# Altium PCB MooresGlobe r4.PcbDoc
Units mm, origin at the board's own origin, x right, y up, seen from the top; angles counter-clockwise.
Board outline 12 x 11 mm, 2 copper layers (Top Layer, Bottom Layer), stack 0.801 mm thick; 11 components, 6 nets, 22 pads, 1 vias.
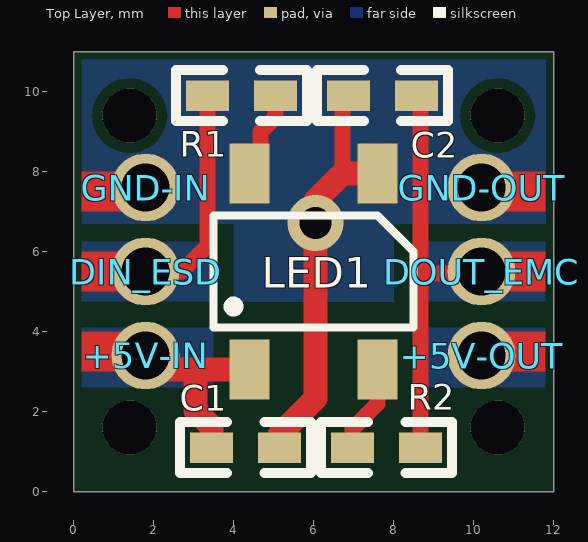
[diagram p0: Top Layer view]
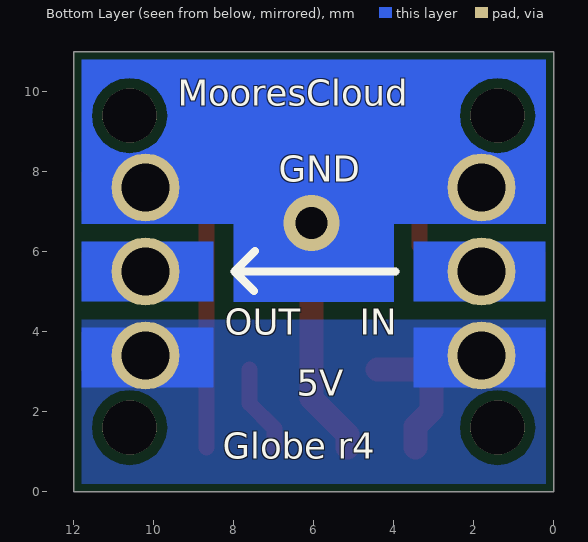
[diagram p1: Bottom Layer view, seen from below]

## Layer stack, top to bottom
Top Layer: signal copper 0.0356
Dielectric: core 0.73, FR-4, Dk 4.8
Bottom Layer: signal copper 0.0356

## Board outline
0,0 12,0 12,11 0,11

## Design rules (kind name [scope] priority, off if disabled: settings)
Clearance [All] p1: gap=0.254
HoleSize [All] p1: absolutevalues=TRUE maxlimit=3 minlimit=0.3 maxpercent=80.000 minpercent=20.000
MinimumSolderMaskSliver [All] p1: minsoldermaskwidth=0.152
PlaneClearance [All] p1: clearance=0.254
PolygonConnect [All] p1: connectstyle=Direct reliefconductorwidth=1.5 reliefentries=4 polygonreliefangle="90 Angle" airgapwidth=0.254
RoutingVias [All] p1: holewidth=0.4 width=0.6 viastyle="Through Hole" minholewidth=0.3 minwidth=0.6 maxholewidth=1 maxwidth=1.27
SilkToSilkClearance [All] p1 off: silktosilkclearance=0
SilkToSolderMaskClearance [IsPad] p1: minsilkscreentomaskgap=0.102 clearancetoexposedcopper=TRUE
SolderMaskExpansion [All] p1: expansion=0.102
Width [All] p1: maxlimit=1.27 minlimit=0.254 preferedwidth=0.254 minimp=50.000000 maximp=50.000000 favimp=50.000000
23 further rules are at their usual default settings.

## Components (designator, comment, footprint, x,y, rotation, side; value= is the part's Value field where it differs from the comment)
+5V-IN "+5V" "Solder Pad"#1 -2.3,1.7 r90 top
+5V-OUT "+5V" "Solder Pad"#2 14.027,2.326 r90 top
C1 "100n" ARA_0603 3.45,1.1 r0 top
C2 "220p" ARA_0603 8.575,9.9 r180 top
DIN_ESD "DIN_ESD" "Solder Pad"#3 -1.95,5.525 r90 top
DOUT_EMC "DOUT_EMC" "Solder Pad"#4 10.2,5.475 r90 top
GND-IN "GND" "Solder Pad"#5 -1.85,9.2 r90 top
GND-OUT "GND" "Solder Pad"#6 10.2,8.925 r90 top
LED1 "WS2812B" PLCC4-LED 6,5.5 r90 top locked
R1 "330R" ARA_0603 5.05,9.9 r180 top
R2 "75R" ARA_0603 6.975,1.1 r0 top

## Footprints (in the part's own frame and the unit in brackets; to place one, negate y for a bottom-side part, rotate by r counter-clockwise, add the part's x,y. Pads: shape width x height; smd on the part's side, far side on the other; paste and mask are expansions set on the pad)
ARA_0603 [mil]
  rect 42x30 smd: 1(0,0) 2(66.91,0)
  silkscreen extent -31,-25 98,25, body extent 0,-16 67,16, height 20
PLCC4-LED [mm] "For WS2812B"
  rect 1.5x1 smd: 1(-2.45,1.6) 2(-2.45,-1.6) 3(2.45,-1.6) 4(2.45,1.6)
  silkscreen extent -1.4,-2.5 1.4,2.5, body extent -2.5,-2.5 2.5,2.5, height 1.61
"Solder Pad"#1 [mm]
  round 1.7 hole 1.2: 1(1.7,-4.1)
"Solder Pad"#2 [mm]
  round 1.7 hole 1.2: 1(1.074,3.827)
"Solder Pad"#3 [mm]
  round 1.7 hole 1.2: 1(-0.025,-3.75)
"Solder Pad"#4 [mm]
  round 1.7 hole 1.2: 1(0.025,0)
"Solder Pad"#5 [mm]
  round 1.7 hole 1.2: 1(-1.6,-3.65)
"Solder Pad"#6 [mm]
  round 1.7 hole 1.2: 1(-1.325,0)

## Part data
+5V-IN +5V-OUT DIN_ESD DOUT_EMC GND-IN GND-OUT: library part "Solder Pad", "Solder pad"
C1: library part CAP, "Capacitor Ceramic 100n 50V Y5V 0603"
C2: library part CAP, "Capacitor Ceramic 470p 50V NPO 0603"
LED1: "WorldSemi WS2812B Smart RGB LED"
R1 R2: library part "Res Semi", "Resistor 100R 0.1W 5% 0603"

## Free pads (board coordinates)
  round 1.35 hole 1.35 unplated mask+0: 0(1.4,1.6) 0(1.4,9.4) 0(10.6,1.6) 0(10.6,9.4)

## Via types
v1: diameter 1.4, hole 0.8, Top Layer to Bottom Layer, tented both sides, 1 vias

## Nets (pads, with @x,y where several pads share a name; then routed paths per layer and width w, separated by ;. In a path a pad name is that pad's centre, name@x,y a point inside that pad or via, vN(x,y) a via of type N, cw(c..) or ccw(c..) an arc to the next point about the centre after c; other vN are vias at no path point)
5V: +5V-IN.1 +5V-OUT.1 C1.1 LED1.1 | length 5.4
  Top Layer w0.6: +5V-IN.1 2.15,3.05 3.05,3.05 ; C1.1 3.45,1.625 3.05,2.025 3.05,3.05 ; LED1.1 3.05,3.05
  Top Layer w0.635: +5V-OUT.1@9.85,3.05 +5V-OUT.1
DIN: LED1.4 R1.1 | length 2.2
  Top Layer w0.4: LED1.4 4.675,8.225 4.675,9 5.05,9.375 R1.1
DIN_ESD: DIN_ESD.1 R1.2 | length 5.6
  Top Layer w0.4: DIN_ESD.1 2.7,5.5 3.35,6.15 R1.2
DOUT: LED1.2 R2.1 | length 2.2
  Top Layer w0.4: R2.1 6.975,1.575 7.6,2.2 LED1.2
DOUT_EMC: C2.1 DOUT_EMC.1 R2.2 | length 10.4
  Top Layer w0.4: C2.1 8.675,9.8 8.675,5.45 ; R2.2 8.675,5.45 ; DOUT_EMC.1@10.15,5.45 8.675,5.45
  Bottom Layer w0.4: DOUT_EMC.1@10.146,5.554 DOUT_EMC.1
GND: C1.2 C2.2 GND-IN.1 GND-OUT.1 LED1.3 | length 11.4
  Top Layer w0.4: 6.725,7.95 6.725,9.749 C2.2
  Top Layer w0.6: C1.2 5.15,1.425 6.05,2.325 v1(6.05,6.713) 6.05,7.275 6.725,7.95 ; 6.35,7.575 6.725,7.95 ; LED1.3@7.575,7.975 LED1.3 ; LED1.3@7.6,8.4 LED1.3 ; 6.725,7.95 LED1.3

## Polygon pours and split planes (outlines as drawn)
5V on Bottom Layer "Botoom Layer-5V" (solid, pour order 4): 11.8,4.3 11.8,0.2 0.2,0.2 0.2,4.3

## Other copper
Top Layer:
  rectangle net DOUT_EMC: 9.75,5 11.8,6
  rectangle net DIN_ESD: 0.2,5 2.25,6
  rectangle net 5V: 0.2,3 2.25,4
  rectangle net GND: 0.2,7 2.25,8
  rectangle net GND: 9.75,7 11.8,8
  rectangle net 5V: 9.75,3 11.8,4
Bottom Layer:
  rectangle net DOUT_EMC: 8.5,4.75 11.8,6.25
  rectangle net DIN_ESD: 0.2,4.75 3.5,6.25
  rectangle net 5V: 0.2,2.6 3.5,4.1
  rectangle net GND: 0.2,6.9 3.5,8.4
  rectangle net GND: 8.5,6.9 11.8,8.4
  rectangle net 5V: 8.5,2.6 11.8,4.1
  region net GND: 11.8,6.7 8,6.7 8,4.75 4,4.75 4,6.7 0.2,6.7 0.2,10.8 11.8,10.8 hole: 10.6,10.337 10.357,10.305 10.131,10.211 9.937,10.063 9.789,9.869 9.695,9.643 9.663,9.4 9.695,9.157 9.789,8.931 9.937,8.737 10.131,8.589 10.357,8.495 10.6,8.463 10.843,8.495 11.069,8.589 11.263,8.737 11.411,8.931 11.505,9.157 11.537,9.4 11.505,9.643 11.411,9.869 11.263,10.063 11.069,10.211 10.843,10.305 hole: 1.4,10.337 1.157,10.305 0.931,10.211 0.737,10.063 0.589,9.869 0.495,9.643 0.463,9.4 0.495,9.157 0.589,8.931 0.737,8.737 0.931,8.589 1.157,8.495 1.4,8.463 1.643,8.495 1.869,8.589 2.063,8.737 2.211,8.931 2.305,9.157 2.337,9.4 2.305,9.643 2.211,9.869 2.063,10.063 1.869,10.211 1.643,10.305

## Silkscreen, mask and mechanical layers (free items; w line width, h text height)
Bottom Overlay:
  lines w0.203: 3.95,5.5 7.975,5.5 ; 7.462,6.013 7.975,5.5 ; 7.488,5.012 7.975,5.5
  text "MooresCloud" at 9.4,9.65 h0.65
  text "GND" at 6.875,7.75 h0.65
  text "IN" at 4.85,3.925 h0.65
  text "OUT" at 8.225,3.925 h0.65
  text "5V" at 6.425,2.4 h0.65
  text "Globe r4" at 8.275,0.825 h0.65
Mechanical 1:
  the board outline again, w0.6
Mechanical 2:
  text "Top Layer Component Keep Out Areas" at 21,4 h1
Mechanical 3:
  text "Bottom Layer Component Keep Out Areas" at 21,2 h1
Drill Drawing:
  lines w0.1: 21,-3.25 79.25,-3.25 ; 21,-1.25 79.25,-1.25 ; 21,7.5 79.25,7.5 ; 21,9.5 79.25,9.5 ; 21,11.5 79.25,11.5 ; 21,13.5 79.25,13.5 ; 21,15.5 79.25,15.5 ; 21,17.5 79.25,17.5 ; 21,19.5 79.25,19.5 ; 21,21.5 79.25,21.5 ; 33.5,-5.25 33.5,1 ; 33.5,5.5 33.5,23.5 ; 0,0 12,0 12,11 0,11 0,0 ; 21,-5.25 79.25,-5.25 79.25,1 21,1 21,-5.25 ; 21,5.5 21,23.5 79.25,23.5 79.25,5.5 21,5.5
  text ".legend" at 22.25,28.75 h1
  text "BOARD SIZE:" at 21.5,22 h1
  text "12.00mm x 11.00mm" at 34.5,22 h1
  text "LAYERS:" at 21.5,20 h1
  text "2" at 34.5,20 h1
  text "MATERIAL:" at 21.5,18 h1
  text "FR4 0.8mm" at 34.5,18 h1
  text "COPPER:" at 21.5,16 h1
  text "35um (after plating)" at 34.5,16 h1
  text "PTH PLATING:" at 21.5,14 h1
  text "20um (minimum)" at 34.5,14 h1
  text "FINISH:" at 21.5,12 h1
  text "ROHS HAL" at 34.5,12 h1
  text "OVERLAY:" at 21.5,10 h1
  text "Black, 2 sides" at 34.5,10 h1
  text "SOLDER MASK:" at 21.5,8 h1
  text "White, 2 sides" at 34.5,8 h1
  text "PROFILING:" at 21.5,6 h1
  text "V-Groove" at 34.5,6 h1
  text "FILE NAME:" at 21.5,-0.75 h1
  text ".Pcb_File_Name_No_Path" at 34.5,-0.75 h1
  text "LAYER:" at 21.5,-2.75 h1
  text ".Plot_File_Name" at 34.5,-2.75 h1
  text "PRINT DATE:" at 21.5,-4.75 h1
  text ".Print_Date" at 34.5,-4.75 h1
Mechanical 20:
  the board outline again, w0.1

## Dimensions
-1,0 to -1,11 on Mechanical 16
0,-1 to 12,-1 on Mechanical 16
0,0 to 12,0 on Drill Drawing
0,0 to 0,11 on Drill Drawing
